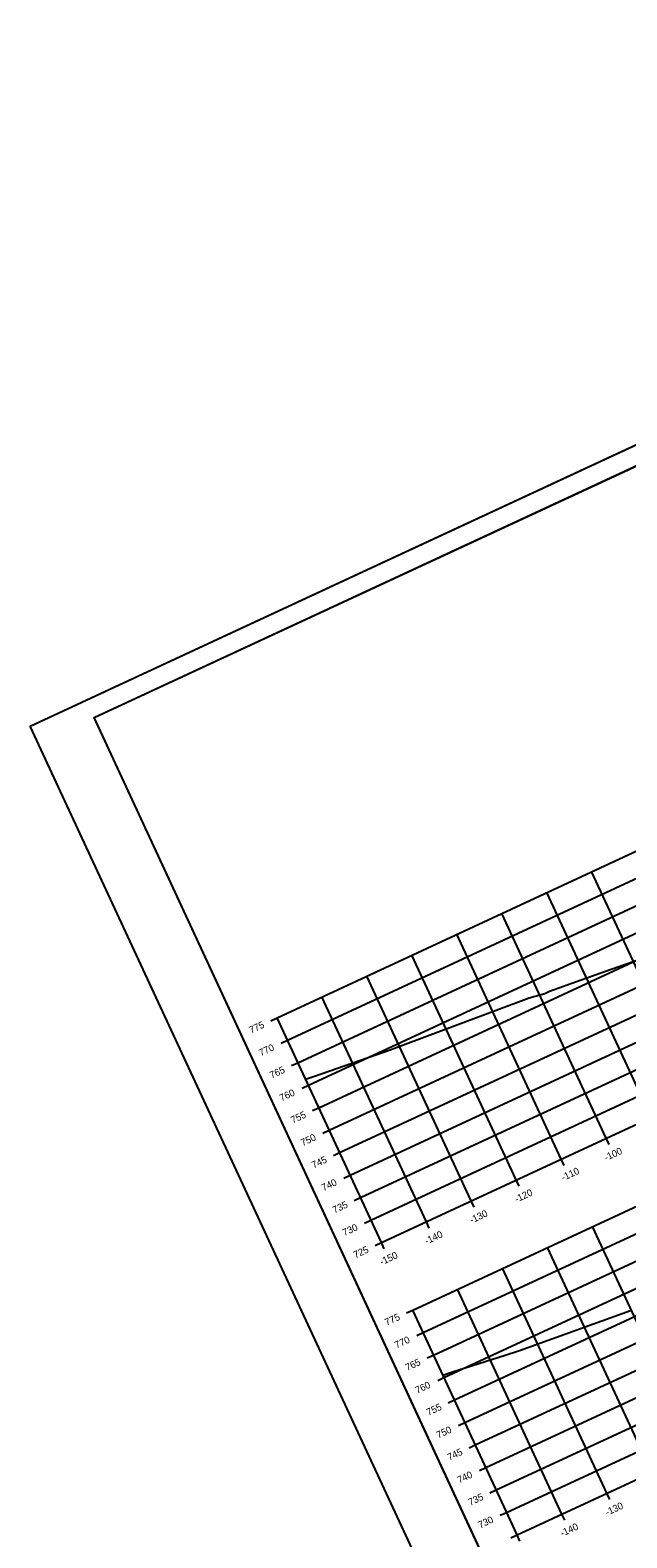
# Model space of a CAD drawing. Extents: x 1354696 to 1366163, y 660729 to 670380.
# Drawn here: x 1358413.5 to 1358533.9, y 666515.9 to 666820.1 of the extents above; entities that cross this region are included whole.
import ezdxf

# ---------------------------------------------------------------- set-up
doc = ezdxf.new("R2010")
doc.units = 0
for name, color, linetype in [('R_Axis', 7, 'Continuous'), ('R_Axis Annot', 7, 'Continuous'), ('R_Border', 7, 'Continuous'), ('R_Exist Surface', 7, 'Continuous'), ('R_Grid', 7, 'Continuous'), ('R_No Plot', 7, 'Continuous')]:
    doc.layers.add(name, color=color, linetype=linetype)

msp = doc.modelspace()

# ---------------------------------------------------------------- linework, layer by layer
at = {"layer": 'R_Axis'}
for p, q in [((1358484.35, 666575.5), (1358756.45, 666701.83)), ((1358511.72, 666516.54), (1358783.82, 666642.87)), ((1358462.02, 666620.26), (1358463.29, 666620.85)), ((1358484.35, 666575.5), (1358463.29, 666620.85)), ((1358464.13, 666615.73), (1358465.4, 666616.31)), ((1358466.24, 666611.19), (1358467.5, 666611.78)), ((1358468.34, 666606.66), (1358469.61, 666607.24)), ((1358470.45, 666602.12), (1358471.72, 666602.71)), ((1358472.55, 666597.59), (1358473.82, 666598.17)), ((1358530.29, 666595.28), (1358529.7, 666596.55)), ((1358474.66, 666593.05), (1358475.93, 666593.64)), ((1358521.22, 666591.07), (1358520.63, 666592.34)), ((1358476.76, 666588.52), (1358478.03, 666589.1)), ((1358512.15, 666586.86), (1358511.56, 666588.13)), ((1358478.87, 666583.98), (1358480.14, 666584.57)), ((1358503.08, 666582.65), (1358502.49, 666583.92)), ((1358480.97, 666579.44), (1358482.24, 666580.03)), ((1358494.01, 666578.44), (1358493.42, 666579.71)), ((1358483.08, 666574.91), (1358484.35, 666575.5)), ((1358484.94, 666574.23), (1358484.35, 666575.5)), ((1358489.4, 666561.3), (1358490.67, 666561.89)), ((1358511.72, 666516.54), (1358490.67, 666561.89)), ((1358491.5, 666556.77), (1358492.77, 666557.36)), ((1358493.61, 666552.23), (1358494.88, 666552.82)), ((1358495.71, 666547.7), (1358496.98, 666548.29)), ((1358497.82, 666543.16), (1358499.09, 666543.75)), ((1358499.92, 666538.63), (1358501.19, 666539.22)), ((1358502.03, 666534.09), (1358503.3, 666534.68)), ((1358504.13, 666529.56), (1358505.4, 666530.15)), ((1358506.24, 666525.02), (1358507.51, 666525.61)), ((1358530.45, 666523.7), (1358529.86, 666524.97)), ((1358508.35, 666520.49), (1358509.62, 666521.08)), ((1358521.38, 666519.48), (1358520.79, 666520.75)), ((1358510.45, 666515.95), (1358511.72, 666516.54)), ((1358512.31, 666515.27), (1358511.72, 666516.54))]:
    msp.add_line(p, q, dxfattribs=at)
at = {"layer": 'R_Border'}
for p, q in [((1358426.37, 666681.39), (1358713.15, 666814.53)), ((1358512.89, 666495.03), (1358426.37, 666681.39))]:
    msp.add_line(p, q, dxfattribs=at)
at = {"layer": 'R_Exist Surface'}
for points in [[(1358469.05, 666608.45), (1358470.84, 666609.07), (1358486.1, 666614.38), (1358487.54, 666614.93), (1358514.16, 666624.85), (1358517.33, 666625.76), (1358518.3, 666626.2), (1358524.66, 666628.53), (1358530.7, 666630.65), (1358545.23, 666635.7)], [(1358496.75, 666548.78), (1358498.53, 666549.34), (1358509.35, 666552.76), (1358512.21, 666553.76), (1358534.6, 666561.77)]]:
    msp.add_lwpolyline(points, dxfattribs=at)
at = {"layer": 'R_Grid'}
for p, q in [((1358463.29, 666620.85), (1358735.4, 666747.18)), ((1358465.4, 666616.31), (1358737.5, 666742.65)), ((1358467.5, 666611.78), (1358739.61, 666738.11)), ((1358469.61, 666607.24), (1358741.71, 666733.58)), ((1358471.72, 666602.71), (1358743.82, 666729.04)), ((1358473.82, 666598.17), (1358745.93, 666724.51)), ((1358475.93, 666593.64), (1358748.03, 666719.97)), ((1358478.03, 666589.1), (1358750.14, 666715.44)), ((1358480.14, 666584.57), (1358752.24, 666710.9)), ((1358482.24, 666580.03), (1358754.35, 666706.36)), ((1358484.35, 666575.5), (1358756.45, 666701.83)), ((1358490.67, 666561.89), (1358762.77, 666688.22)), ((1358492.77, 666557.36), (1358764.87, 666683.69)), ((1358494.88, 666552.82), (1358766.98, 666679.15)), ((1358496.98, 666548.29), (1358769.09, 666674.62)), ((1358499.09, 666543.75), (1358771.19, 666670.08)), ((1358501.19, 666539.22), (1358773.3, 666665.55)), ((1358503.3, 666534.68), (1358775.4, 666661.01)), ((1358505.4, 666530.15), (1358777.51, 666656.48)), ((1358507.51, 666525.61), (1358779.61, 666651.94)), ((1358547.84, 666604.98), (1358526.78, 666650.33)), ((1358509.62, 666521.08), (1358781.72, 666647.41)), ((1358538.77, 666600.77), (1358517.71, 666646.12)), ((1358529.7, 666596.55), (1358508.64, 666641.91)), ((1358511.72, 666516.54), (1358783.82, 666642.87)), ((1358520.63, 666592.34), (1358499.57, 666637.69)), ((1358511.56, 666588.13), (1358490.5, 666633.48)), ((1358502.49, 666583.92), (1358481.43, 666629.27)), ((1358493.42, 666579.71), (1358472.36, 666625.06)), ((1358484.35, 666575.5), (1358463.29, 666620.85)), ((1358548, 666533.39), (1358526.95, 666578.74)), ((1358538.93, 666529.18), (1358517.88, 666574.53)), ((1358529.86, 666524.97), (1358508.81, 666570.32)), ((1358520.79, 666520.75), (1358499.74, 666566.11)), ((1358511.72, 666516.54), (1358490.67, 666561.89))]:
    msp.add_line(p, q, dxfattribs=at)
at = {"layer": 'R_No Plot'}
msp.add_line((1358413.48, 666679.7), (1358715.82, 666820.07), dxfattribs=at)
for points in [[(1358413.47, 666679.7), (1358715.82, 666820.07), (1358805.65, 666626.57), (1358503.31, 666486.2)], [(1358638.54, 666779.89), (1358656.33, 666788.16), (1358660.49, 666779.19), (1358675.11, 666785.98), (1358696.15, 666795.75), (1358708.11, 666770.26), (1358729.16, 666780.03), (1358799.67, 666628.18), (1358512.89, 666495.03), (1358426.37, 666681.39)]]:
    msp.add_lwpolyline(points, close=True, dxfattribs=at)

# ---------------------------------------------------------------- texts
at = {"layer": 'R_Axis Annot'}
for s, p in [('775', (1358458.05, 666617.64)), ('770', (1358460.04, 666613.06)), ('765', (1358462.2, 666608.55)), ('760', (1358464.2, 666603.96)), ('755', (1358466.47, 666599.5)), ('750', (1358468.47, 666594.92)), ('-100', (1358529.7, 666591.93)), ('745', (1358470.68, 666590.43)), ('-110', (1358521.04, 666587.9)), ('740', (1358472.68, 666585.85)), ('-120', (1358511.61, 666583.53)), ('735', (1358474.89, 666581.36)), ('-130', (1358502.54, 666579.32)), ('730', (1358476.89, 666576.78)), ('-140', (1358493.47, 666575.1)), ('725', (1358479.1, 666572.29)), ('-150', (1358484.4, 666570.89)), ('775', (1358485.42, 666558.69)), ('770', (1358487.42, 666554.1)), ('765', (1358489.57, 666549.59)), ('760', (1358491.57, 666545)), ('755', (1358493.84, 666540.55)), ('750', (1358495.84, 666535.96)), ('745', (1358498.05, 666531.48)), ('740', (1358500.05, 666526.89)), ('735', (1358502.27, 666522.41)), ('-130', (1358529.91, 666520.36)), ('730', (1358504.26, 666517.82)), ('-140', (1358520.84, 666516.15))]:
    msp.add_text(s, height=1.4, rotation=24.9042, dxfattribs=at).set_placement(p)

doc.saveas('drawing.dxf')
